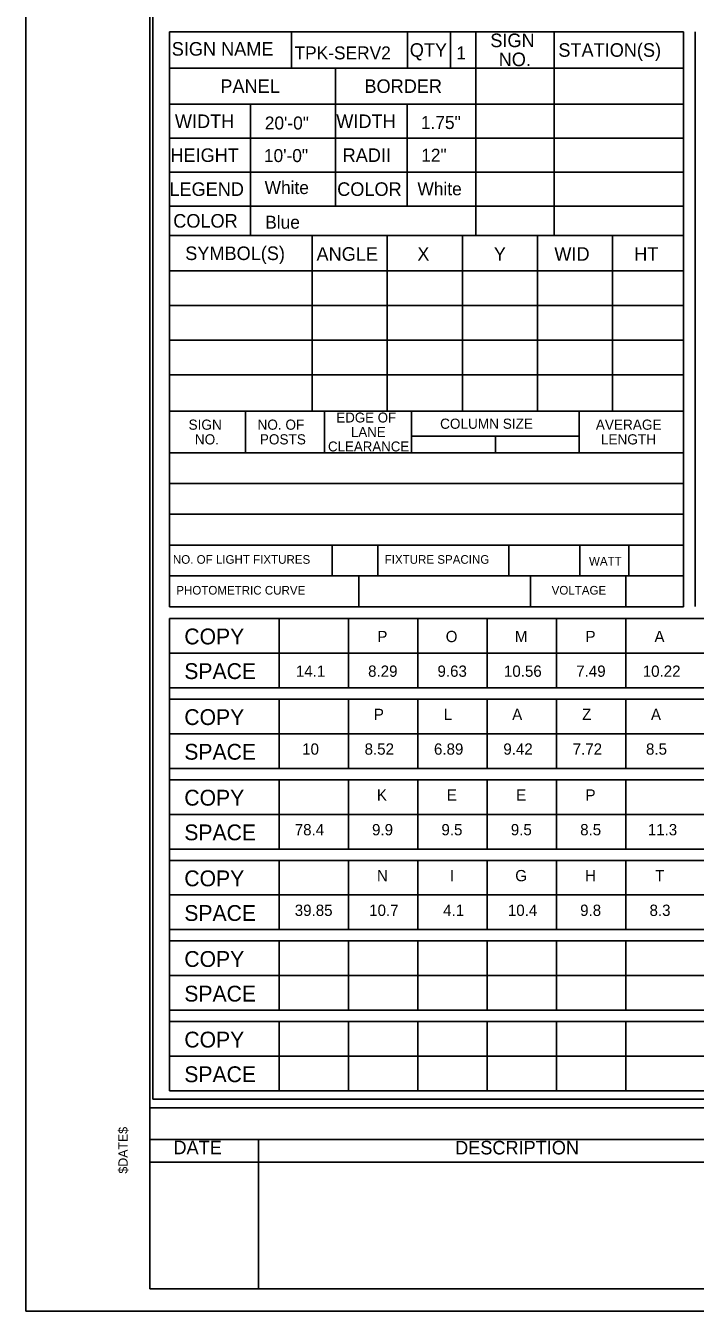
# Model space of a CAD drawing. Extents: x 17890628 to 17890817, y 17897493 to 17897992.
# Drawn here: x 17890655.6 to 17890684.6, y 17897492.8 to 17897548.6 of the extents above; entities that cross this region are included whole.
import ezdxf

# ---------------------------------------------------------------- set-up
doc = ezdxf.new("R2010")
doc.units = 0
for name, color, linetype in [('GSSign', 7, 'Continuous'), ('PlotBorder_dp', 7, 'Continuous'), ('SheetBorder_dp', 7, 'Continuous'), ('SheetLines_dp', 7, 'Continuous'), ('SheetLinesMisc1_dp', 7, 'Continuous'), ('SheetLinesMisc2_dp', 7, 'Continuous'), ('TextMinor', 7, 'Continuous'), ('TextMisc', 7, 'Continuous')]:
    doc.layers.add(name, color=color, linetype=linetype)

msp = doc.modelspace()

# ---------------------------------------------------------------- linework, layer by layer
at = {"layer": 'PlotBorder_dp'}
msp.add_lwpolyline([(17890655.57, 17897492.839), (17890817.319, 17897492.839), (17890817.319, 17897596.75), (17890655.57, 17897596.75)], close=True, dxfattribs=at)
at = {"layer": 'SheetBorder_dp'}
for p, q in [((17890660.962, 17897595.77), (17890660.962, 17897493.819)), ((17890660.962, 17897501.661), (17890811.928, 17897501.661)), ((17890660.962, 17897493.819), (17890811.928, 17897493.819))]:
    msp.add_line(p, q, dxfattribs=at)
at = {"layer": 'SheetLines_dp'}
for p, q in [((17890660.962, 17897500.289), (17890717.427, 17897500.289)), ((17890665.667, 17897500.289), (17890665.667, 17897493.819)), ((17890660.962, 17897499.309), (17890717.427, 17897499.309))]:
    msp.add_line(p, q, dxfattribs=at)
at = {"layer": 'SheetLinesMisc1_dp'}
for p, q in [((17890667.098, 17897546.756), (17890667.098, 17897548.325)), ((17890672.146, 17897548.325), (17890672.146, 17897546.756)), ((17890673.998, 17897548.325), (17890673.998, 17897546.756)), ((17890675.102, 17897548.325), (17890675.102, 17897539.49)), ((17890678.497, 17897548.325), (17890678.497, 17897539.49)), ((17890661.804, 17897546.756), (17890684.115, 17897546.756)), ((17890669.015, 17897546.756), (17890669.015, 17897540.755)), ((17890661.804, 17897545.188), (17890684.115, 17897545.188)), ((17890665.33, 17897545.188), (17890665.33, 17897539.49)), ((17890672.126, 17897545.172), (17890672.126, 17897540.755)), ((17890661.804, 17897543.715), (17890684.115, 17897543.715)), ((17890661.804, 17897542.243), (17890684.115, 17897542.243)), ((17890661.804, 17897540.77), (17890684.115, 17897540.77)), ((17890661.804, 17897539.49), (17890684.115, 17897539.49)), ((17890668, 17897539.49), (17890668, 17897531.871)), ((17890671.26, 17897539.49), (17890671.26, 17897531.871)), ((17890674.52, 17897539.49), (17890674.52, 17897531.871)), ((17890677.78, 17897539.461), (17890677.78, 17897531.871)), ((17890681.04, 17897539.461), (17890681.04, 17897531.871)), ((17890661.809, 17897537.957), (17890684.115, 17897537.957)), ((17890661.809, 17897536.454), (17890684.115, 17897536.454)), ((17890661.809, 17897534.951), (17890684.115, 17897534.951)), ((17890661.809, 17897533.447), (17890684.115, 17897533.447)), ((17890661.804, 17897531.871), (17890684.115, 17897531.871)), ((17890665.115, 17897531.871), (17890665.115, 17897530.075)), ((17890668.537, 17897531.871), (17890668.537, 17897530.075)), ((17890672.315, 17897531.871), (17890672.315, 17897530.075)), ((17890679.591, 17897531.871), (17890679.591, 17897530.075)), ((17890672.315, 17897530.794), (17890679.586, 17897530.794)), ((17890675.951, 17897530.794), (17890675.951, 17897530.075)), ((17890661.804, 17897530.075), (17890684.115, 17897530.075)), ((17890661.804, 17897528.739), (17890684.115, 17897528.739)), ((17890661.804, 17897527.404), (17890684.115, 17897527.404)), ((17890661.804, 17897526.068), (17890684.115, 17897526.068)), ((17890661.804, 17897524.732), (17890684.115, 17897524.732))]:
    msp.add_line(p, q, dxfattribs=at)
at = {"layer": 'SheetLinesMisc2_dp'}
for p, q in [((17890661.083, 17897595.691), (17890661.083, 17897502.033)), ((17890661.804, 17897523.397), (17890661.804, 17897548.325)), ((17890661.804, 17897548.325), (17890684.115, 17897548.325)), ((17890684.115, 17897548.325), (17890684.115, 17897523.397)), ((17890684.628, 17897548.326), (17890684.628, 17897523.435)), ((17890661.804, 17897526.067), (17890684.11, 17897526.067)), ((17890668.863, 17897526.067), (17890668.863, 17897524.732)), ((17890670.855, 17897526.067), (17890670.855, 17897524.732)), ((17890676.53, 17897526.067), (17890676.53, 17897524.732)), ((17890679.617, 17897526.067), (17890679.617, 17897524.732)), ((17890681.746, 17897526.067), (17890681.746, 17897524.732)), ((17890661.804, 17897524.732), (17890684.11, 17897524.732)), ((17890670.032, 17897524.732), (17890670.032, 17897523.397)), ((17890677.475, 17897524.732), (17890677.475, 17897523.397)), ((17890681.617, 17897524.732), (17890681.617, 17897523.397)), ((17890661.804, 17897523.397), (17890684.11, 17897523.397)), ((17890661.804, 17897523.397), (17890684.115, 17897523.397)), ((17890684.628, 17897523.435), (17890684.628, 17897523.401)), ((17890661.804, 17897522.886), (17890735.8, 17897522.886)), ((17890661.804, 17897502.398), (17890661.804, 17897522.886)), ((17890666.568, 17897522.886), (17890666.568, 17897519.88)), ((17890669.578, 17897522.886), (17890669.578, 17897519.88)), ((17890672.588, 17897522.886), (17890672.588, 17897519.88)), ((17890675.598, 17897522.886), (17890675.598, 17897519.88)), ((17890678.608, 17897522.886), (17890678.608, 17897519.88)), ((17890681.618, 17897522.886), (17890681.618, 17897519.88)), ((17890661.804, 17897521.384), (17890735.8, 17897521.384)), ((17890661.804, 17897519.88), (17890735.8, 17897519.88)), ((17890661.804, 17897519.389), (17890735.8, 17897519.389)), ((17890666.568, 17897519.389), (17890666.568, 17897516.383)), ((17890669.578, 17897519.389), (17890669.578, 17897516.383)), ((17890672.588, 17897519.389), (17890672.588, 17897516.383)), ((17890675.598, 17897519.389), (17890675.598, 17897516.383)), ((17890678.608, 17897519.389), (17890678.608, 17897516.383)), ((17890681.618, 17897519.389), (17890681.618, 17897516.383)), ((17890661.804, 17897517.886), (17890735.8, 17897517.886)), ((17890661.804, 17897516.383), (17890735.8, 17897516.383)), ((17890661.804, 17897515.893), (17890735.8, 17897515.893)), ((17890666.568, 17897515.893), (17890666.568, 17897512.887)), ((17890669.578, 17897515.893), (17890669.578, 17897512.887)), ((17890672.588, 17897515.893), (17890672.588, 17897512.887)), ((17890675.598, 17897515.893), (17890675.598, 17897512.887)), ((17890678.608, 17897515.893), (17890678.608, 17897512.887)), ((17890681.618, 17897515.893), (17890681.618, 17897512.887)), ((17890661.804, 17897514.39), (17890735.8, 17897514.39)), ((17890661.804, 17897512.887), (17890735.8, 17897512.887)), ((17890661.804, 17897512.396), (17890735.8, 17897512.396)), ((17890666.568, 17897512.396), (17890666.568, 17897509.39)), ((17890669.578, 17897512.396), (17890669.578, 17897509.39)), ((17890672.588, 17897512.396), (17890672.588, 17897509.39)), ((17890675.598, 17897512.396), (17890675.598, 17897509.39)), ((17890678.608, 17897512.396), (17890678.608, 17897509.39)), ((17890681.618, 17897512.396), (17890681.618, 17897509.39)), ((17890661.804, 17897510.894), (17890735.8, 17897510.894)), ((17890661.804, 17897509.39), (17890735.8, 17897509.39)), ((17890661.804, 17897508.9), (17890735.8, 17897508.9)), ((17890666.568, 17897508.9), (17890666.568, 17897505.894)), ((17890669.578, 17897508.9), (17890669.578, 17897505.894)), ((17890672.588, 17897508.9), (17890672.588, 17897505.894)), ((17890675.598, 17897508.9), (17890675.598, 17897505.894)), ((17890678.608, 17897508.9), (17890678.608, 17897505.894)), ((17890681.618, 17897508.9), (17890681.618, 17897505.894)), ((17890661.804, 17897507.396), (17890735.8, 17897507.396)), ((17890661.804, 17897505.894), (17890735.8, 17897505.894)), ((17890661.804, 17897505.403), (17890735.8, 17897505.403)), ((17890666.568, 17897505.403), (17890666.568, 17897502.398)), ((17890669.578, 17897505.403), (17890669.578, 17897502.398)), ((17890672.588, 17897505.403), (17890672.588, 17897502.398)), ((17890675.598, 17897505.403), (17890675.598, 17897502.398)), ((17890678.608, 17897505.403), (17890678.608, 17897502.398)), ((17890681.618, 17897505.403), (17890681.618, 17897502.398)), ((17890661.804, 17897503.9), (17890735.8, 17897503.9)), ((17890661.083, 17897502.033), (17890811.539, 17897502.033)), ((17890661.804, 17897502.398), (17890735.8, 17897502.398))]:
    msp.add_line(p, q, dxfattribs=at)

# ---------------------------------------------------------------- texts
at = {"layer": 'GSSign'}
for s, height, p in [('TPK-SERV2', 0.5624, (17890667.236, 17897547.134)), ('1', 0.562, (17890674.256, 17897547.132)), ('20\'-0"', 0.5624, (17890665.946, 17897544.093)), ('1.75"', 0.5624, (17890672.719, 17897544.114)), ('10\'-0"', 0.5624, (17890665.908, 17897542.68)), ('12"', 0.5624, (17890672.734, 17897542.696)), ('White', 0.5624, (17890665.94, 17897541.293)), ('White', 0.5624, (17890672.571, 17897541.238)), ('Blue', 0.5624, (17890665.965, 17897539.79)), ('P', 0.49, (17890670.831, 17897521.859)), ('O', 0.49, (17890673.797, 17897521.859)), ('M', 0.49, (17890676.798, 17897521.859)), ('P', 0.49, (17890679.863, 17897521.859)), ('A', 0.49, (17890682.856, 17897521.859)), ('14.1', 0.4902, (17890667.294, 17897520.356)), ('8.29', 0.4902, (17890670.429, 17897520.356)), ('9.63', 0.4902, (17890673.44, 17897520.356)), ('10.56', 0.4902, (17890676.324, 17897520.356)), ('7.49', 0.4902, (17890679.46, 17897520.356)), ('10.22', 0.4902, (17890682.347, 17897520.356)), ('P', 0.49, (17890670.678, 17897518.481)), ('L', 0.49, (17890673.706, 17897518.481)), ('A', 0.49, (17890676.682, 17897518.481)), ('Z', 0.49, (17890679.715, 17897518.481)), ('A', 0.49, (17890682.703, 17897518.481)), ('10', 0.4902, (17890667.567, 17897516.978)), ('8.52', 0.4902, (17890670.277, 17897516.978)), ('6.89', 0.4902, (17890673.287, 17897516.978)), ('9.42', 0.4902, (17890676.297, 17897516.978)), ('7.72', 0.4902, (17890679.308, 17897516.978)), ('8.5', 0.4902, (17890682.489, 17897516.978)), ('K', 0.49, (17890670.809, 17897514.984)), ('E', 0.49, (17890673.843, 17897514.984)), ('E', 0.49, (17890676.854, 17897514.984)), ('P', 0.49, (17890679.863, 17897514.984)), ('78.4', 0.4902, (17890667.246, 17897513.481)), ('9.9', 0.4902, (17890670.6, 17897513.481)), ('9.5', 0.4902, (17890673.611, 17897513.481)), ('9.5', 0.4902, (17890676.622, 17897513.481)), ('8.5', 0.4902, (17890679.632, 17897513.481)), ('11.3', 0.4902, (17890682.566, 17897513.481)), ('N', 0.49, (17890670.813, 17897511.488)), ('I', 0.49, (17890673.975, 17897511.488)), ('G', 0.49, (17890676.815, 17897511.488)), ('H', 0.49, (17890679.844, 17897511.488)), ('T', 0.49, (17890682.887, 17897511.488)), ('39.85', 0.4902, (17890667.246, 17897509.985)), ('10.7', 0.4902, (17890670.475, 17897509.985)), ('4.1', 0.4902, (17890673.685, 17897509.985)), ('10.4', 0.4902, (17890676.495, 17897509.985)), ('9.8', 0.4902, (17890679.631, 17897509.985)), ('8.3', 0.4902, (17890682.642, 17897509.985))]:
    msp.add_text(s, height=height, dxfattribs=at).set_placement(p)
at = {"layer": 'TextMinor'}
for s, height, p in [('SIGN NAME', 0.5882, (17890661.908, 17897547.295)), ('QTY', 0.5882, (17890672.237, 17897547.246)), ('SIGN', 0.5882, (17890675.733, 17897547.664)), ('STATION(S)', 0.5882, (17890678.686, 17897547.246)), ('NO.', 0.5882, (17890676.096, 17897546.84)), ('PANEL', 0.5882, (17890664.018, 17897545.678)), ('BORDER', 0.5882, (17890670.271, 17897545.678)), ('WIDTH', 0.5882, (17890662.045, 17897544.157)), ('WIDTH', 0.5882, (17890669.048, 17897544.157)), ('HEIGHT', 0.5882, (17890661.848, 17897542.685)), ('RADII', 0.5882, (17890669.324, 17897542.685)), ('LEGEND', 0.5882, (17890661.806, 17897541.213)), ('COLOR', 0.5882, (17890669.088, 17897541.213)), ('COLOR', 0.5882, (17890661.973, 17897539.836)), ('SYMBOL(S)', 0.5882, (17890662.494, 17897538.43)), ('ANGLE', 0.5882, (17890668.19, 17897538.401)), ('X', 0.588, (17890672.565, 17897538.401)), ('Y', 0.588, (17890675.885, 17897538.401)), ('WID', 0.5882, (17890678.512, 17897538.401)), ('HT', 0.5882, (17890681.978, 17897538.401)), ('EDGE OF', 0.4313, (17890669.052, 17897531.385)), ('SIGN', 0.4411, (17890662.637, 17897531.071)), ('NO. OF', 0.4411, (17890665.63, 17897531.071)), ('LANE', 0.4313, (17890669.685, 17897530.757)), ('COLUMN SIZE', 0.44113, (17890673.553, 17897531.112)), ('AVERAGE', 0.4411, (17890680.311, 17897531.071)), ('NO.', 0.4411, (17890662.91, 17897530.434)), ('POSTS', 0.4411, (17890665.73, 17897530.434)), ('CLEARANCE', 0.4313, (17890668.69, 17897530.13)), ('LENGTH', 0.4411, (17890680.529, 17897530.434)), ('NO. OF LIGHT FIXTURES', 0.37485, (17890661.958, 17897525.258)), ('FIXTURE SPACING', 0.37485, (17890671.149, 17897525.258)), ('WATT', 0.3749, (17890680.015, 17897525.183)), ('PHOTOMETRIC CURVE', 0.37485, (17890662.105, 17897523.922)), ('VOLTAGE', 0.3749, (17890678.394, 17897523.922)), ('COPY', 0.6862, (17890662.454, 17897521.762)), ('SPACE', 0.6862, (17890662.454, 17897520.259)), ('COPY', 0.6862, (17890662.454, 17897518.264)), ('SPACE', 0.6862, (17890662.454, 17897516.761)), ('COPY', 0.6862, (17890662.454, 17897514.769)), ('SPACE', 0.6862, (17890662.454, 17897513.266)), ('COPY', 0.6862, (17890662.454, 17897511.271)), ('SPACE', 0.6862, (17890662.454, 17897509.769)), ('COPY', 0.6862, (17890662.454, 17897507.775)), ('SPACE', 0.6862, (17890662.454, 17897506.272)), ('COPY', 0.6862, (17890662.454, 17897504.279)), ('SPACE', 0.6862, (17890662.454, 17897502.776))]:
    msp.add_text(s, height=height, dxfattribs=at).set_placement(p)
msp.add_text('$DATE$', height=0.4008, rotation=90, dxfattribs=at).set_placement((17890659.995, 17897498.811))
at = {"layer": 'TextMisc'}
for s, height, rotation, p in [('DATE', 0.5882, 359.8693, (17890661.982, 17897499.652)), ('DESCRIPTION', 0.58818, 0.0498, (17890674.206, 17897499.64))]:
    msp.add_text(s, height=height, rotation=rotation, dxfattribs=at).set_placement(p)

doc.saveas('drawing.dxf')
